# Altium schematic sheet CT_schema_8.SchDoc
size 287 x 160 mm
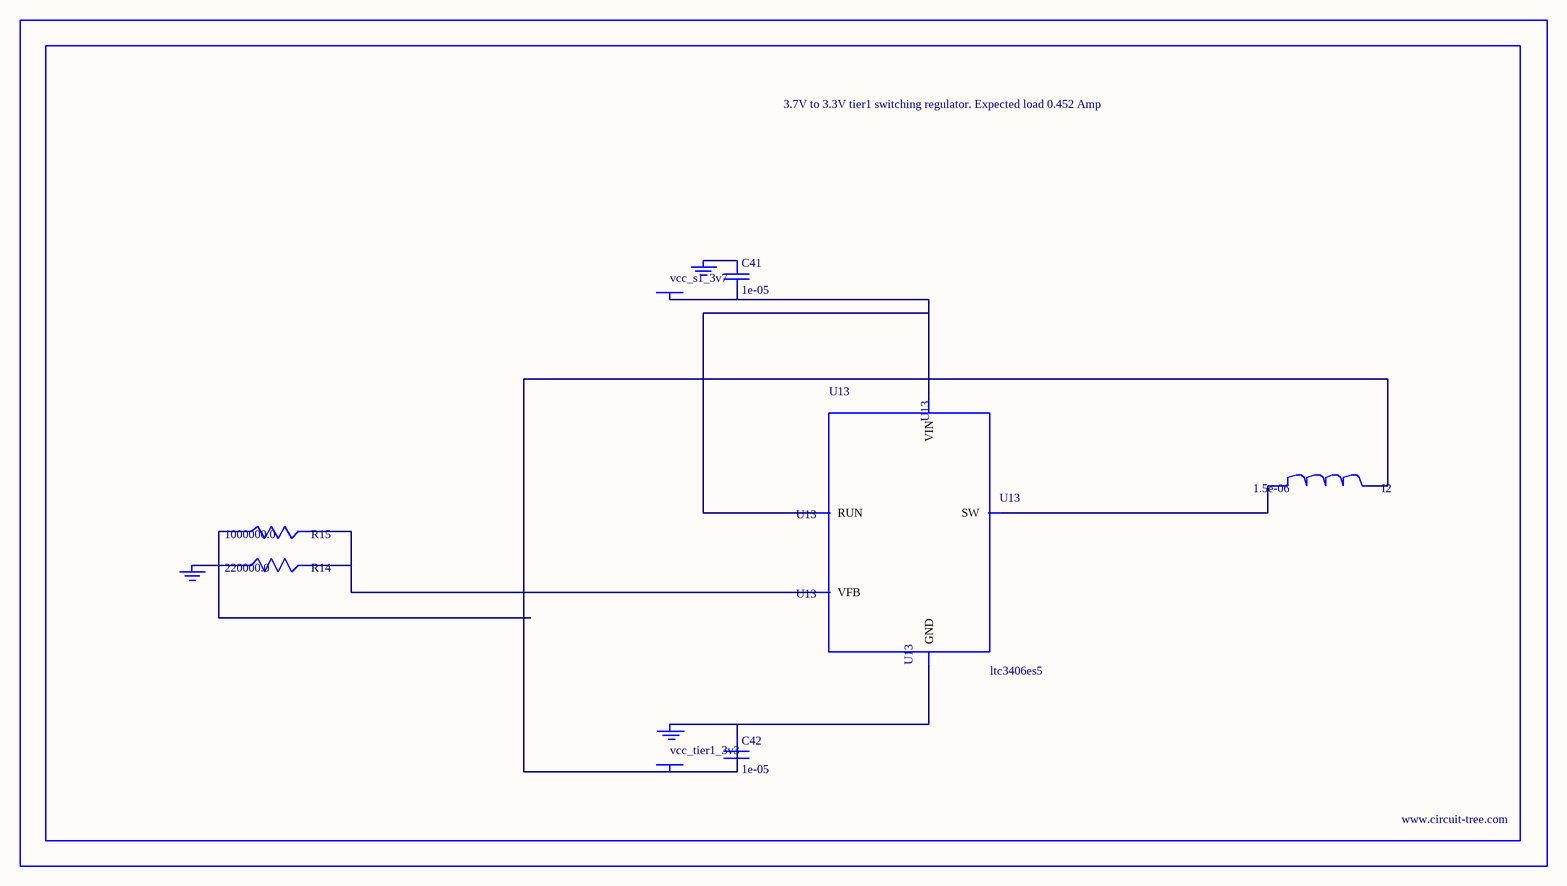
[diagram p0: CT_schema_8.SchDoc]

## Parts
BORDER7  (no value)
C41  1e-05  [C0805]
C42  1e-05  [C0805]
GND_INSTANCE_7_0  (no value)
GND_INSTANCE_7_1  (no value)
GND_INSTANCE_7_2  (no value)
I2  1.5e-06  [L0806]
POWER_INSTANCE_7_0  vcc_tier1_3v3
POWER_INSTANCE_7_1  vcc_s1_3v7
R14  220000.0  [R0603]
R15  1000000.0  [R0603]
U13  ltc3406es5  [TSOT-23-5]

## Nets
NetC41_1: C41.1 GND_INSTANCE_7_1.0(GND)
NetC41_2: C41.2 POWER_INSTANCE_7_1.0(PWR) U13.1(RUN) U13.4(VIN)
NetC42_1: C42.1 GND_INSTANCE_7_0.0(GND) U13.2(GND)
NetC42_2: C42.2 I2.2 POWER_INSTANCE_7_0.0(PWR) R15.1
NetGND_INSTANCE_7_2_0: GND_INSTANCE_7_2.0(GND) R14.1
NetI2_1: I2.1 U13.3(SW)
NetR14_2: R14.2 R15.2 U13.5(VFB)

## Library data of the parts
BORDER7 = BORDER_PAGE7
C41 C42 = C0805C106K8RACTU
GND_INSTANCE_7_0-GND_INSTANCE_7_2 = GND
I2 = L0806C1R5MDWIT
POWER_INSTANCE_7_0 POWER_INSTANCE_7_1 = PWR
R14 = RC0603JR-07220KL
R15 = RC0603JR-071ML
